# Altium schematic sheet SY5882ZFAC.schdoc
size 127 x 101 mm
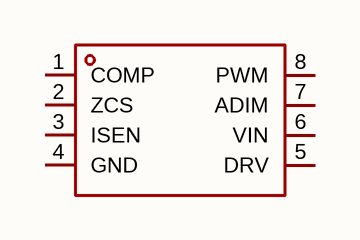
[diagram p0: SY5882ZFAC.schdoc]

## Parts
U?  sy5882zfac  [SOIC-8_L4.9-W3.9-P1.27-LS6.0-BL]  (value not drawn)

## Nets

Not connected (* = marked no-connect by the designer): U? 1(COMP) 2(ZCS) 3(ISEN) 4(GND) 5(DRV) 6(VIN) 7(ADIM) 8(PWM)

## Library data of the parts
U? = sy5882zfac: 功能类型:-;工作电压:380V~450V;输出电压:42V;输出电流:1A;输出类型:-;; Manufacturer: Silergy(矽力杰); AddInBom: yes; ModelId: e81d2f7d937b4a6ab1dca543ff5d56a4; ModelName: SOIC-8_L4.9-W3.9-H1.7-LS6.0-P1.27; ModelTransform: 192.913,236.22,0,0,0,0,0,0,0; Output Voltage: 42V; Output Current: 1A; Frequency - Switching: 55kHz; Synchronous Rectifier: 否; Number of Outputs: 1; Topology: 反激式; Quiescent Current: 34uA; Switch tube (built-in/external): 外置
